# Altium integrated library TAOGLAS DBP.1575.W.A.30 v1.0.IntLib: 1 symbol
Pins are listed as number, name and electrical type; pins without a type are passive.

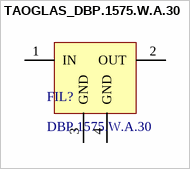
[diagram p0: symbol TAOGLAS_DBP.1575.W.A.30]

## TAOGLAS_DBP.1575.W.A.30
designator FIL?, comment DBP.1575.W.A.30
1575MHz 5.8*5.1*2.8mm, Bandwidth 10MHz; ComponentLibStatus: Created; MFG: Taoglas; Temp_High: +85C; Temp_Low: -40C
footprint TAOGLAS_DBP.1575.W.A.30 (1575MHz 5.8*5.1*2.8mm, Bandwidth 10MHz)
pins: 1 IN, 2 OUT, 3 GND, 4 GND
